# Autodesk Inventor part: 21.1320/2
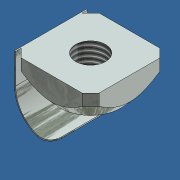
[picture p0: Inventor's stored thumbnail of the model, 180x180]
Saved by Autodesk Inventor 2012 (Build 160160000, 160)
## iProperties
Created: 2006-12
Part Number: 21.1320/2
Document SubType Name: Modeling
Designer: Andy Moles
Material: Steel, Mild
Density: 7.86 g/cm^3
Mass: 5.5784 g
Surface Area: 8.43697 cm^2
Volume: 0.70972 cm^3
Description: M5 SQUARE NUT POS FXG
Vendor: S
Author: Andy Moles
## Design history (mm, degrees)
sketch "Sketch2"
  geometry: L1 (-5.086, -6.5)-(5.086, -6.5); L2 (6.5, -5.086)-(6.5, 5.086); L3 (5.086, 6.5)-(-5.086, 6.5); L4 (-6.5, 5.086)-(-6.5, -5.086); L5 (-6.5, 6.5)-(6.5, -6.5); L6 (5.086, 6.5)-(6.5, 5.086); L7 (0, -6.5)-(0, 6.5); L8 (-6.5, 0)-(6.5, 0); L9 (-5.086, 6.5)-(-6.5, 5.086); L10 (-5.086, -6.5)-(-6.5, -5.086); L11 (5.086, -6.5)-(6.5, -5.086); C1 r 2.5 at (0, 0); 2 further points
  constraints: 22 end point, 6 symmetric about line, 4 parallel, 3 midpoint, 2 coincident, 2 perpendicular, 1 centre point, 1 horizontal
  dimensions: "THREAD" = 5 diameter of C1; "d3" = 45 deg angle of L3 L6 (derived); "d4" = 2 distance of L3.start L2.end
extrude "Extrusion1" new body sketch "Sketch2" distance "d5" = 5.5; taper "d6" = 0 deg
workplane "Work Plane1"
sketch "Sketch4"
  geometry: L1 (10.692, 0)-(5.692, 0) reference; L2 (8.192, 0)-(13.192, 0); L3 (16.385, 5.5)-(16.385, 3.5); L4 (13.192, 0)-(16.797, 3.952); L5 (13.192, 0)-(16.385, 0); L6 (16.385, 3.5)-(16.385, 0); L7 (16.797, 3.952)-(16.797, -0.412); L8 (16.797, -0.412)-(13.192, -0.412); L9 (13.192, -0.412)-(13.192, 0); L10 (8.192, 5.5)-(8.192, 0); L11 (16.385, 5.5)-(16.385, 0) reference; L12 (16.385, 3.5)-(17.502, 3.5); L13 (9.192, 5.5)-(16.385, 5.5) reference
  constraints: 20 end point, 6 perpendicular, 1 collinear, 1 midpoint, 1 parallel, 1 point on line
  dimensions: "d10" = 5 distance of L2.start L2.end; "d15" = 2 distance between parallel lines of L12 L13
revolve "Revolution1" sketch "Sketch4" stored, may be unused: angle "d12" = 90 deg
thread "Thread1" dims "d13" = 10, "d14" = 0
sketch "Sketch6"
  geometry: L1 (6.5, 0)-(6.5, 6.006); L2 (6.5, 0)-(6.5, -5); L3 (6.5, 0)-(6.7, 0); L4 (6.7, 0)-(6.7, -5); L5 (0.9, -10.6)-(0.9, -10.8); L6 (6.5, 0)-(6.5, -1.933); L7 (-5.086, 0)-(5.086, 0); A1 r 5.374 centre (1.131, -5.231) between (0.9, -10.6) and (6.5, -5); A2 r 5.574 centre (1.131, -5.231) between (0.9, -10.8) and (6.7, -5); 3 further points
  constraints: 14 end point, 4 point on circle, 3 collinear, 2 centre point, 2 parallel, 2 perpendicular, 1 coincident
  dimensions: "d21" = 5 distance of L1.start L2.end; "d22" = 0.2 distance of L1.start L3.end; "d23" = 0.2 distance of L5.start L5.end; "d24" = 10.8 distance from line of L5.end L3; "d25" = 5.37434 radius of A1
extrude "Extrusion3" join sketch "Sketch6" stored distance "d26" = 12; taper "d27" = 0 deg
fillet "Fillet2" dims "d28" = 2
fillet "Fillet3" dims "d29" = 2
body "Solid1"
